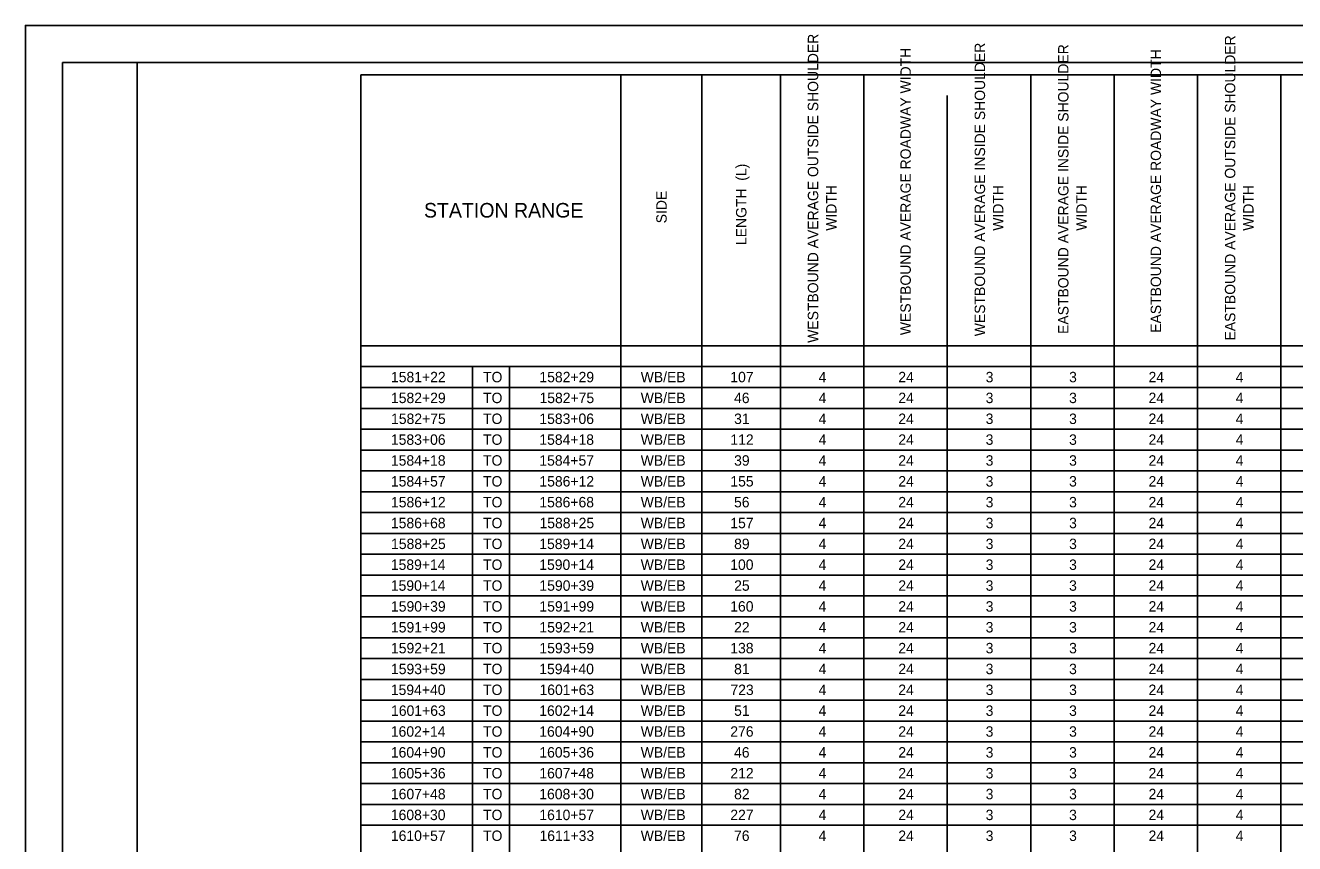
# Model space of a CAD drawing. Extents: x 0 to 34, y 0 to 22.
# Drawn here: x 0 to 17.04, y 11.01 to 22 of the extents above; entities that cross this region are included whole.
import ezdxf

# ---------------------------------------------------------------- set-up
doc = ezdxf.new("R2010")
doc.units = 0
for name, color, linetype in [('SH_Border', 7, 'Continuous'), ('SH_Cut_Line', 7, 'Continuous'), ('SH_Data', 7, 'Continuous'), ('SH_Text', 7, 'Continuous')]:
    doc.layers.add(name, color=color, linetype=linetype)

msp = doc.modelspace()

# ---------------------------------------------------------------- linework, layer by layer
at = {"layer": 'SH_Border'}
for points in [[(0.5, 21.5), (1.5, 21.5), (1.5, 0.5), (0.5, 0.5)], [(1.5, 21.5), (33.5, 21.5), (33.5, 0.5), (1.5, 0.5)]]:
    msp.add_lwpolyline(points, close=True, dxfattribs=at)
at = {"layer": 'SH_Cut_Line'}
msp.add_lwpolyline([(0, 0), (34, 0), (34, 22), (0, 22)], close=True, dxfattribs=at)
at = {"layer": 'SH_Data'}
for p, q in [((4.506, 21.337), (29.179, 21.337)), ((4.506, 21.337), (4.506, 0.617)), ((7.997, 21.337), (7.997, 1.177)), ((9.084, 21.337), (9.084, 1.177)), ((10.139, 21.337), (10.139, 1.177)), ((11.259, 21.337), (11.259, 1.177)), ((13.499, 21.337), (13.499, 0.617)), ((14.619, 21.337), (14.619, 0.617)), ((15.739, 21.337), (15.739, 0.617)), ((16.859, 21.337), (16.859, 0.617)), ((12.379, 21.057), (12.379, 0.617)), ((4.506, 17.697), (29.179, 17.697)), ((4.506, 17.417), (29.179, 17.417)), ((6.004, 17.417), (6.004, 1.177)), ((6.499, 17.417), (6.499, 1.177)), ((4.506, 17.137), (29.179, 17.137)), ((4.506, 16.857), (29.179, 16.857)), ((4.506, 16.577), (29.179, 16.577)), ((4.506, 16.297), (29.179, 16.297)), ((4.506, 16.017), (29.179, 16.017)), ((4.506, 15.737), (29.179, 15.737)), ((4.506, 15.457), (29.179, 15.457)), ((4.506, 15.177), (29.179, 15.177)), ((4.506, 14.897), (29.179, 14.897)), ((4.506, 14.617), (29.179, 14.617)), ((4.506, 14.337), (29.179, 14.337)), ((4.506, 14.057), (29.179, 14.057)), ((4.506, 13.777), (29.179, 13.777)), ((4.506, 13.497), (29.179, 13.497)), ((4.506, 13.217), (29.179, 13.217)), ((4.506, 12.937), (29.179, 12.937)), ((4.506, 12.657), (29.179, 12.657)), ((4.506, 12.377), (29.179, 12.377)), ((4.506, 12.097), (29.179, 12.097)), ((4.506, 11.817), (29.179, 11.817)), ((4.506, 11.537), (29.179, 11.537)), ((4.506, 11.257), (29.179, 11.257))]:
    msp.add_line(p, q, dxfattribs=at)

# ---------------------------------------------------------------- texts
at = {"layer": 'SH_Text'}
for s, p in [('WESTBOUND AVERAGE OUTSIDE SHOULDER ', (10.646, 17.737)), ('EASTBOUND AVERAGE OUTSIDE SHOULDER ', (16.246, 17.768)), ('WESTBOUND AVERAGE ROADWAY WIDTH', (11.889, 17.84)), ('WESTBOUND AVERAGE INSIDE SHOULDER ', (12.886, 17.825)), ('EASTBOUND AVERAGE INSIDE SHOULDER ', (14.006, 17.856)), ('EASTBOUND AVERAGE ROADWAY WIDTH', (15.249, 17.871)), ('LENGTH  (L)', (9.682, 19.05)), ('SIDE', (8.611, 19.342)), ('WIDTH', (10.891, 19.242)), ('WIDTH', (13.131, 19.242)), ('WIDTH', (14.251, 19.242)), ('WIDTH', (16.491, 19.242))]:
    msp.add_text(s, height=0.14, rotation=90, dxfattribs=at).set_placement(p)
for s, height, p in [('STATION RANGE', 0.196, (5.352, 19.419)), ('1581+22', 0.14, (4.909, 17.207)), ('TO', 0.14, (6.145, 17.207)), ('1582+29', 0.14, (6.902, 17.207)), ('WB/EB', 0.14, (8.262, 17.207)), ('107', 0.14, (9.465, 17.207)), ('4', 0.14, (10.651, 17.207)), ('24', 0.14, (11.721, 17.207)), ('3', 0.14, (12.894, 17.207)), ('3', 0.14, (14.014, 17.207)), ('24', 0.14, (15.081, 17.207)), ('4', 0.14, (16.251, 17.207)), ('1582+29', 0.14, (4.909, 16.927)), ('TO', 0.14, (6.145, 16.927)), ('1582+75', 0.14, (6.903, 16.927)), ('WB/EB', 0.14, (8.262, 16.927)), ('46', 0.14, (9.515, 16.927)), ('4', 0.14, (10.651, 16.927)), ('24', 0.14, (11.721, 16.927)), ('3', 0.14, (12.894, 16.927)), ('3', 0.14, (14.014, 16.927)), ('24', 0.14, (15.081, 16.927)), ('4', 0.14, (16.251, 16.927)), ('1582+75', 0.14, (4.91, 16.647)), ('TO', 0.14, (6.145, 16.647)), ('1583+06', 0.14, (6.901, 16.647)), ('WB/EB', 0.14, (8.262, 16.647)), ('31', 0.14, (9.516, 16.647)), ('4', 0.14, (10.651, 16.647)), ('24', 0.14, (11.721, 16.647)), ('3', 0.14, (12.894, 16.647)), ('3', 0.14, (14.014, 16.647)), ('24', 0.14, (15.081, 16.647)), ('4', 0.14, (16.251, 16.647)), ('1583+06', 0.14, (4.908, 16.367)), ('TO', 0.14, (6.145, 16.367)), ('1584+18', 0.14, (6.901, 16.367)), ('WB/EB', 0.14, (8.262, 16.367)), ('112', 0.14, (9.466, 16.367)), ('4', 0.14, (10.651, 16.367)), ('24', 0.14, (11.721, 16.367)), ('3', 0.14, (12.894, 16.367)), ('3', 0.14, (14.014, 16.367)), ('24', 0.14, (15.081, 16.367)), ('4', 0.14, (16.251, 16.367)), ('1584+18', 0.14, (4.908, 16.087)), ('TO', 0.14, (6.145, 16.087)), ('1584+57', 0.14, (6.901, 16.087)), ('WB/EB', 0.14, (8.262, 16.087)), ('39', 0.14, (9.516, 16.087)), ('4', 0.14, (10.651, 16.087)), ('24', 0.14, (11.721, 16.087)), ('3', 0.14, (12.894, 16.087)), ('3', 0.14, (14.014, 16.087)), ('24', 0.14, (15.081, 16.087)), ('4', 0.14, (16.251, 16.087)), ('1584+57', 0.14, (4.908, 15.807)), ('TO', 0.14, (6.145, 15.807)), ('1586+12', 0.14, (6.902, 15.807)), ('WB/EB', 0.14, (8.262, 15.807)), ('155', 0.14, (9.466, 15.807)), ('4', 0.14, (10.651, 15.807)), ('24', 0.14, (11.721, 15.807)), ('3', 0.14, (12.894, 15.807)), ('3', 0.14, (14.014, 15.807)), ('24', 0.14, (15.081, 15.807)), ('4', 0.14, (16.251, 15.807)), ('1586+12', 0.14, (4.909, 15.527)), ('TO', 0.14, (6.145, 15.527)), ('1586+68', 0.14, (6.901, 15.527)), ('WB/EB', 0.14, (8.262, 15.527)), ('56', 0.14, (9.515, 15.527)), ('4', 0.14, (10.651, 15.527)), ('24', 0.14, (11.721, 15.527)), ('3', 0.14, (12.894, 15.527)), ('3', 0.14, (14.014, 15.527)), ('24', 0.14, (15.081, 15.527)), ('4', 0.14, (16.251, 15.527)), ('1586+68', 0.14, (4.908, 15.247)), ('TO', 0.14, (6.145, 15.247)), ('1588+25', 0.14, (6.903, 15.247)), ('WB/EB', 0.14, (8.262, 15.247)), ('157', 0.14, (9.465, 15.247)), ('4', 0.14, (10.651, 15.247)), ('24', 0.14, (11.721, 15.247)), ('3', 0.14, (12.894, 15.247)), ('3', 0.14, (14.014, 15.247)), ('24', 0.14, (15.081, 15.247)), ('4', 0.14, (16.251, 15.247)), ('1588+25', 0.14, (4.91, 14.967)), ('TO', 0.14, (6.145, 14.967)), ('1589+14', 0.14, (6.9, 14.967)), ('WB/EB', 0.14, (8.262, 14.967)), ('89', 0.14, (9.516, 14.967)), ('4', 0.14, (10.651, 14.967)), ('24', 0.14, (11.721, 14.967)), ('3', 0.14, (12.894, 14.967)), ('3', 0.14, (14.014, 14.967)), ('24', 0.14, (15.081, 14.967)), ('4', 0.14, (16.251, 14.967)), ('1589+14', 0.14, (4.907, 14.687)), ('TO', 0.14, (6.145, 14.687)), ('1590+14', 0.14, (6.9, 14.687)), ('WB/EB', 0.14, (8.262, 14.687)), ('100', 0.14, (9.464, 14.687)), ('4', 0.14, (10.651, 14.687)), ('24', 0.14, (11.721, 14.687)), ('3', 0.14, (12.894, 14.687)), ('3', 0.14, (14.014, 14.687)), ('24', 0.14, (15.081, 14.687)), ('4', 0.14, (16.251, 14.687)), ('1590+14', 0.14, (4.907, 14.407)), ('TO', 0.14, (6.145, 14.407)), ('1590+39', 0.14, (6.902, 14.407)), ('WB/EB', 0.14, (8.262, 14.407)), ('25', 0.14, (9.517, 14.407)), ('4', 0.14, (10.651, 14.407)), ('24', 0.14, (11.721, 14.407)), ('3', 0.14, (12.894, 14.407)), ('3', 0.14, (14.014, 14.407)), ('24', 0.14, (15.081, 14.407)), ('4', 0.14, (16.251, 14.407)), ('1590+39', 0.14, (4.909, 14.127)), ('TO', 0.14, (6.145, 14.127)), ('1591+99', 0.14, (6.902, 14.127)), ('WB/EB', 0.14, (8.262, 14.127)), ('160', 0.14, (9.464, 14.127)), ('4', 0.14, (10.651, 14.127)), ('24', 0.14, (11.721, 14.127)), ('3', 0.14, (12.894, 14.127)), ('3', 0.14, (14.014, 14.127)), ('24', 0.14, (15.081, 14.127)), ('4', 0.14, (16.251, 14.127)), ('1591+99', 0.14, (4.909, 13.847)), ('TO', 0.14, (6.145, 13.847)), ('1592+21', 0.14, (6.902, 13.847)), ('WB/EB', 0.14, (8.262, 13.847)), ('22', 0.14, (9.516, 13.847)), ('4', 0.14, (10.651, 13.847)), ('24', 0.14, (11.721, 13.847)), ('3', 0.14, (12.894, 13.847)), ('3', 0.14, (14.014, 13.847)), ('24', 0.14, (15.081, 13.847)), ('4', 0.14, (16.251, 13.847)), ('1592+21', 0.14, (4.909, 13.567)), ('TO', 0.14, (6.145, 13.567)), ('1593+59', 0.14, (6.902, 13.567)), ('WB/EB', 0.14, (8.262, 13.567)), ('138', 0.14, (9.465, 13.567)), ('4', 0.14, (10.651, 13.567)), ('24', 0.14, (11.721, 13.567)), ('3', 0.14, (12.894, 13.567)), ('3', 0.14, (14.014, 13.567)), ('24', 0.14, (15.081, 13.567)), ('4', 0.14, (16.251, 13.567)), ('1593+59', 0.14, (4.909, 13.287)), ('TO', 0.14, (6.145, 13.287)), ('1594+40', 0.14, (6.9, 13.287)), ('WB/EB', 0.14, (8.262, 13.287)), ('81', 0.14, (9.516, 13.287)), ('4', 0.14, (10.651, 13.287)), ('24', 0.14, (11.721, 13.287)), ('3', 0.14, (12.894, 13.287)), ('3', 0.14, (14.014, 13.287)), ('24', 0.14, (15.081, 13.287)), ('4', 0.14, (16.251, 13.287)), ('1594+40', 0.14, (4.907, 13.007)), ('TO', 0.14, (6.145, 13.007)), ('1601+63', 0.14, (6.903, 13.007)), ('WB/EB', 0.14, (8.262, 13.007)), ('723', 0.14, (9.467, 13.007)), ('4', 0.14, (10.651, 13.007)), ('24', 0.14, (11.721, 13.007)), ('3', 0.14, (12.894, 13.007)), ('3', 0.14, (14.014, 13.007)), ('24', 0.14, (15.081, 13.007)), ('4', 0.14, (16.251, 13.007)), ('1601+63', 0.14, (4.91, 12.727)), ('TO', 0.14, (6.145, 12.727)), ('1602+14', 0.14, (6.9, 12.727)), ('WB/EB', 0.14, (8.262, 12.727)), ('51', 0.14, (9.516, 12.727)), ('4', 0.14, (10.651, 12.727)), ('24', 0.14, (11.721, 12.727)), ('3', 0.14, (12.894, 12.727)), ('3', 0.14, (14.014, 12.727)), ('24', 0.14, (15.081, 12.727)), ('4', 0.14, (16.251, 12.727)), ('1602+14', 0.14, (4.907, 12.447)), ('TO', 0.14, (6.145, 12.447)), ('1604+90', 0.14, (6.9, 12.447)), ('WB/EB', 0.14, (8.262, 12.447)), ('276', 0.14, (9.465, 12.447)), ('4', 0.14, (10.651, 12.447)), ('24', 0.14, (11.721, 12.447)), ('3', 0.14, (12.894, 12.447)), ('3', 0.14, (14.014, 12.447)), ('24', 0.14, (15.081, 12.447)), ('4', 0.14, (16.251, 12.447)), ('1604+90', 0.14, (4.907, 12.167)), ('TO', 0.14, (6.145, 12.167)), ('1605+36', 0.14, (6.901, 12.167)), ('WB/EB', 0.14, (8.262, 12.167)), ('46', 0.14, (9.515, 12.167)), ('4', 0.14, (10.651, 12.167)), ('24', 0.14, (11.721, 12.167)), ('3', 0.14, (12.894, 12.167)), ('3', 0.14, (14.014, 12.167)), ('24', 0.14, (15.081, 12.167)), ('4', 0.14, (16.251, 12.167)), ('1605+36', 0.14, (4.908, 11.887)), ('TO', 0.14, (6.145, 11.887)), ('1607+48', 0.14, (6.901, 11.887)), ('WB/EB', 0.14, (8.262, 11.887)), ('212', 0.14, (9.466, 11.887)), ('4', 0.14, (10.651, 11.887)), ('24', 0.14, (11.721, 11.887)), ('3', 0.14, (12.894, 11.887)), ('3', 0.14, (14.014, 11.887)), ('24', 0.14, (15.081, 11.887)), ('4', 0.14, (16.251, 11.887)), ('1607+48', 0.14, (4.908, 11.607)), ('TO', 0.14, (6.145, 11.607)), ('1608+30', 0.14, (6.9, 11.607)), ('WB/EB', 0.14, (8.262, 11.607)), ('82', 0.14, (9.516, 11.607)), ('4', 0.14, (10.651, 11.607)), ('24', 0.14, (11.721, 11.607)), ('3', 0.14, (12.894, 11.607)), ('3', 0.14, (14.014, 11.607)), ('24', 0.14, (15.081, 11.607)), ('4', 0.14, (16.251, 11.607)), ('1608+30', 0.14, (4.907, 11.327)), ('TO', 0.14, (6.145, 11.327)), ('1610+57', 0.14, (6.901, 11.327)), ('WB/EB', 0.14, (8.262, 11.327)), ('227', 0.14, (9.465, 11.327)), ('4', 0.14, (10.651, 11.327)), ('24', 0.14, (11.721, 11.327)), ('3', 0.14, (12.894, 11.327)), ('3', 0.14, (14.014, 11.327)), ('24', 0.14, (15.081, 11.327)), ('4', 0.14, (16.251, 11.327)), ('1610+57', 0.14, (4.908, 11.047)), ('TO', 0.14, (6.145, 11.047)), ('1611+33', 0.14, (6.903, 11.047)), ('WB/EB', 0.14, (8.262, 11.047)), ('76', 0.14, (9.515, 11.047)), ('4', 0.14, (10.651, 11.047)), ('24', 0.14, (11.721, 11.047)), ('3', 0.14, (12.894, 11.047)), ('3', 0.14, (14.014, 11.047)), ('24', 0.14, (15.081, 11.047)), ('4', 0.14, (16.251, 11.047))]:
    msp.add_text(s, height=height, dxfattribs=at).set_placement(p)

doc.saveas('drawing.dxf')
